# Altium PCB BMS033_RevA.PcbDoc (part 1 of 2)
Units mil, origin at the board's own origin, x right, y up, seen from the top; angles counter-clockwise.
Board outline 3000 x 3000 mil, 2 copper layers (Layer 1 - Top Layer, Layer 2 - Bottom Layer), stack 32 mil thick; 87 components, 36 nets, 183 pads, 163 vias.
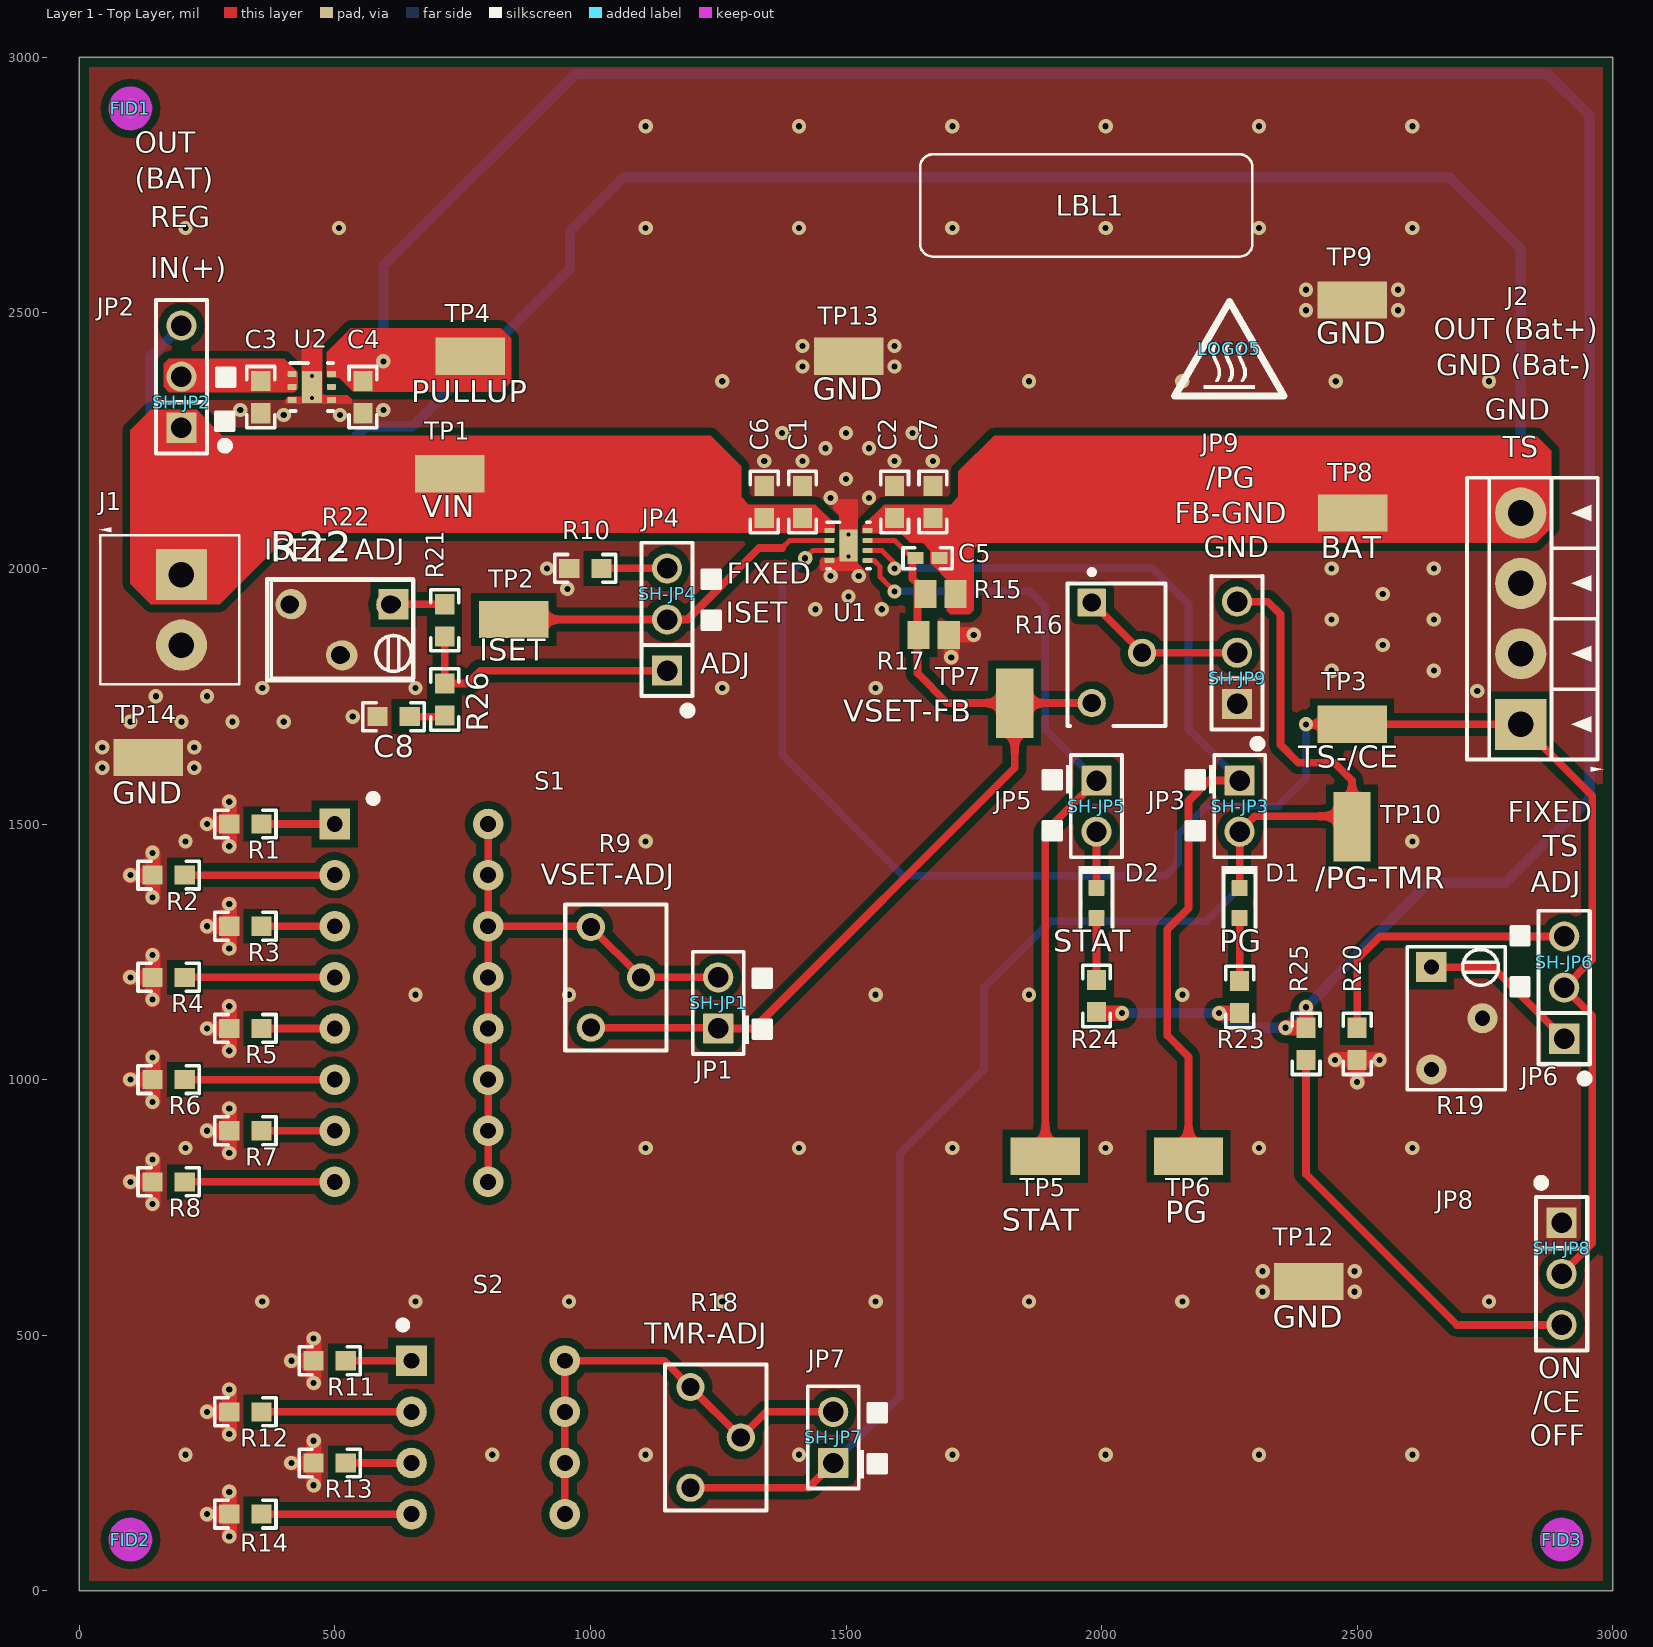
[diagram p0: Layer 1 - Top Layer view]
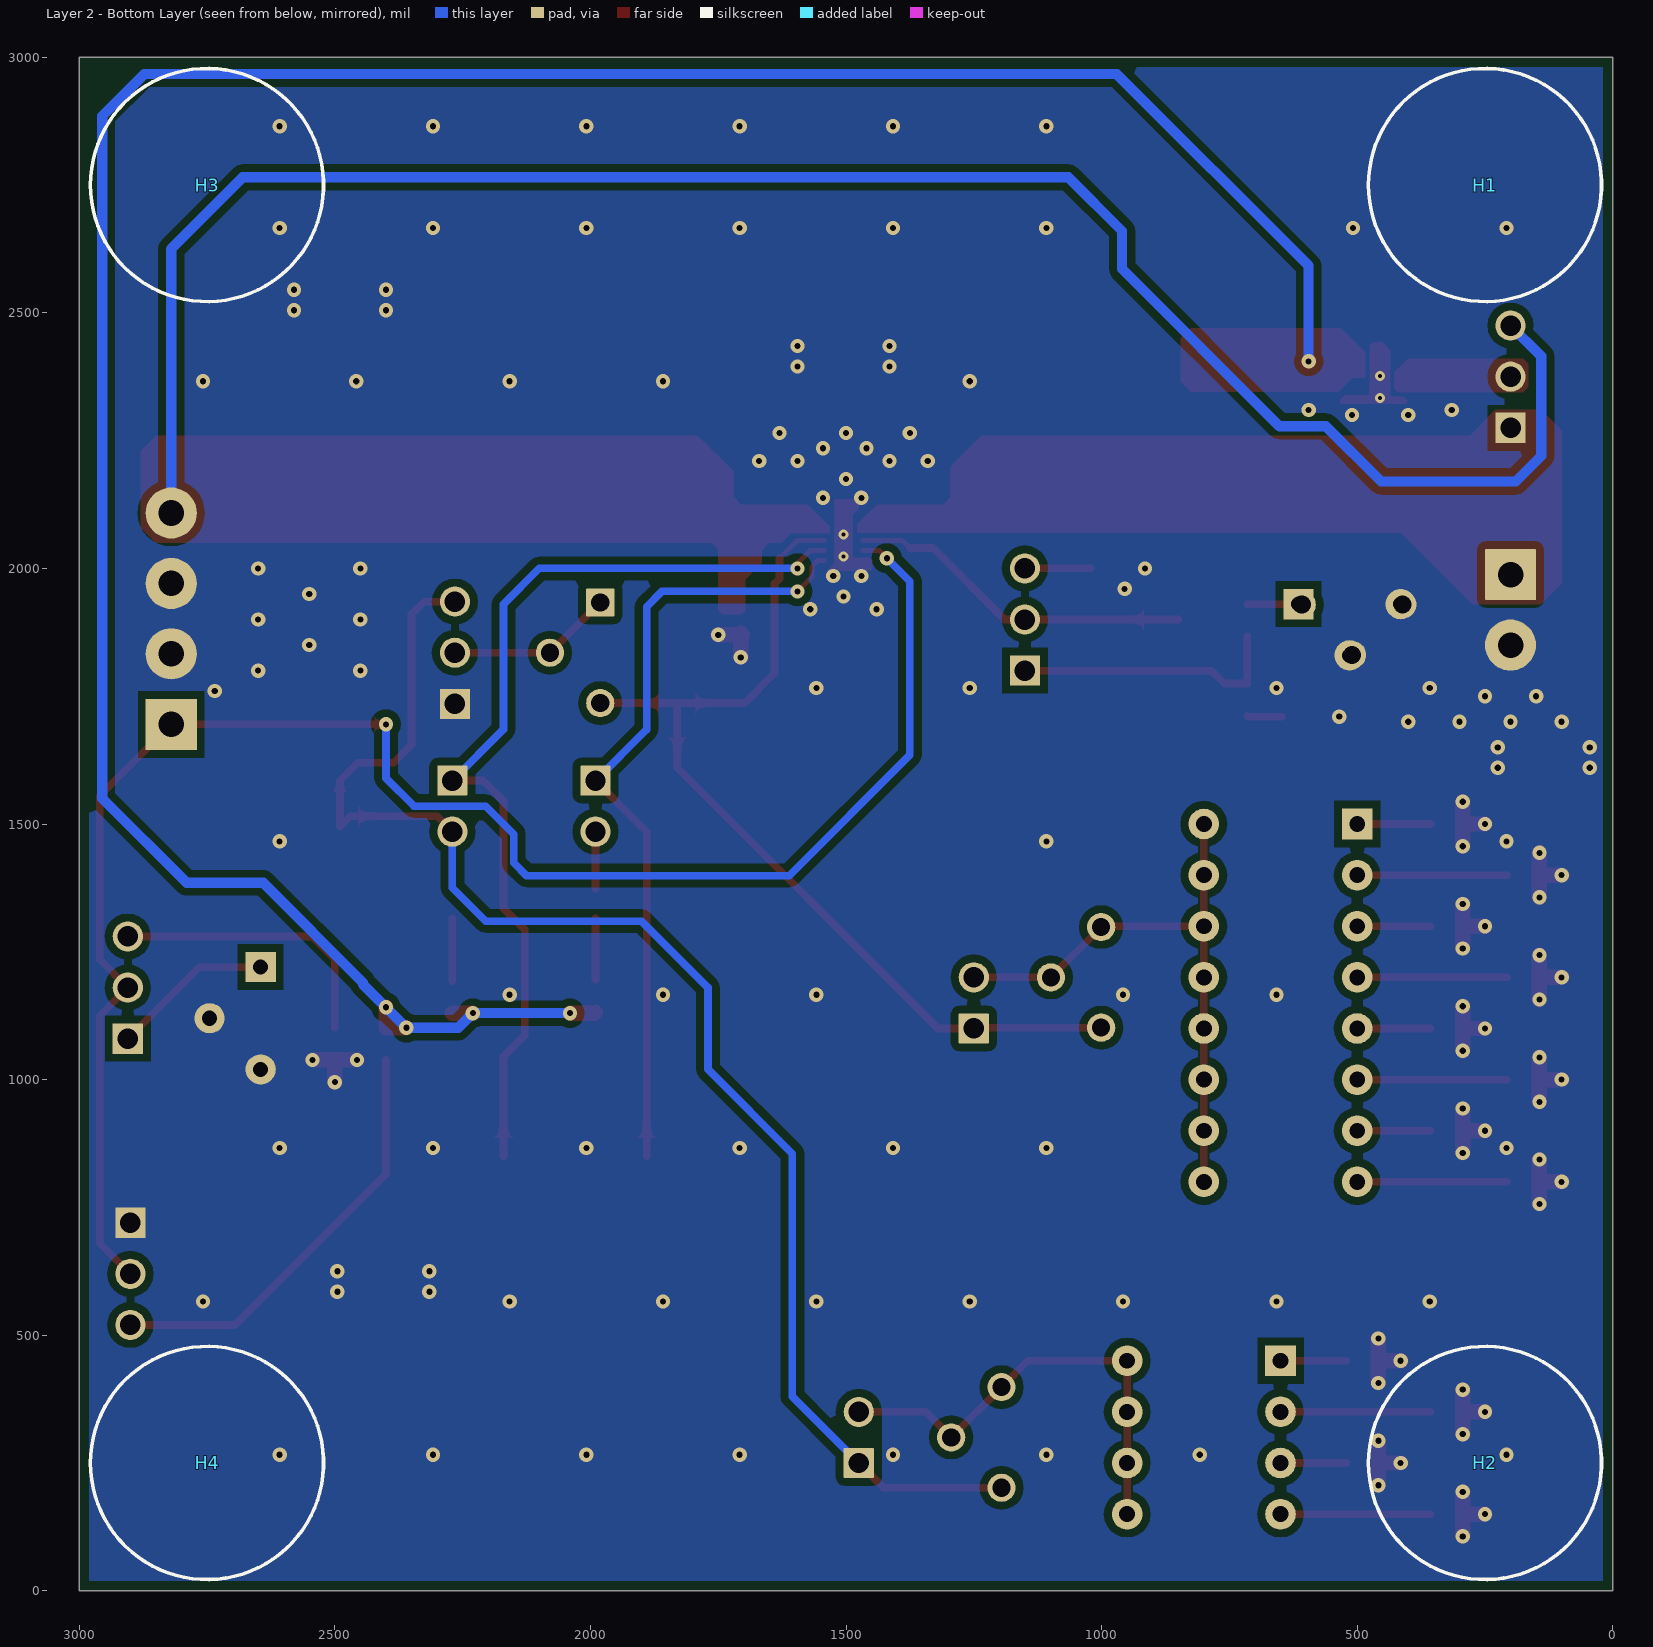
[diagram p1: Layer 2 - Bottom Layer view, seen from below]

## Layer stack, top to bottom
Top Solder: solder mask 0.4, Solder Resist, Dk 3.5
Layer 1 - Top Layer: signal copper 2.8
Dielectric 1: core 26.4, FR-4 High-TG, Dk 4.4
Layer 2 - Bottom Layer: signal copper 2.8
Bottom Solder: solder mask 0.4, Solder Resist, Dk 3.5

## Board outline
0,0 3000,0 3000,3000 0,3000

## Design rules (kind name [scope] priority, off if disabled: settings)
AcuteAngle [All] p1: minimum=4.50000000000000E+0001 checktracksonly=FALSE
AssemblyTestPointUsage [All] p1: valid=2
BoardOutlineClearance BoardOutlineClearance_MountingHoles [OnCopper and InComponentClass('Mounting Holes')] p1: gap=40 ignorepadtopadclearanceinfootprint=FALSE
BoardOutlineClearance BoardOutlineClearance_Poly [OnCopper and IsPoly] p2: gap=20 ignorepadtopadclearanceinfootprint=FALSE
BoardOutlineClearance [OnCopper and Not InComponentClass('Logo') and not InComponentClass('FiducialMark') and not InRegion(1000,500,4000,800) and not InPoly] p3: gap=20 ignorepadtopadclearanceinfootprint=FALSE
Clearance Clearance_Keepouts [((IsTrack Or IsArc) And Not InPoly) And IsFree and IsKeepOut vs ((IsTrack Or IsArc) And Not InPoly) And IsFree and IsKeepOut] p1: gap=0 ignorepadtopadclearanceinfootprint=FALSE
Clearance Clearance_Poly [InPolygon] p2: gap=15 ignorepadtopadclearanceinfootprint=FALSE
Clearance Clearance_FiducialMark [IsKeepOut and InComponentClass('FiducialMark') vs IsPad and InComponentClass('FiducialMark')] p3: gap=0 ignorepadtopadclearanceinfootprint=FALSE
Clearance [All] p4: gap=7.87 ignorepadtopadclearanceinfootprint=FALSE except(0: Arc-Hole Track-Hole SMDPad-Hole THPad-Hole Via-Hole Fill-Hole Poly-Hole Region-Hole Text-Hole)
ComponentClearance ComponentClearance_MountingHoles_FiducialMarks [InComponentClass('Mounting Holes') vs InComponentClass('FiducialMark')] p1: gap=50 collisioncheckmode=3 verticalgap=10 showdistances=FALSE
ComponentClearance ComponentClearance_Shunt [InComponentClass('Header') vs InComponentClass('Shunt')] p2: gap=0 collisioncheckmode=3 verticalgap=0 showdistances=FALSE
ComponentClearance ComponentClearance_Logo [InComponentClass('Logo')] p3: gap=50 collisioncheckmode=3 verticalgap=10 showdistances=FALSE
ComponentClearance ComponentClearance_ScrewToNut [(HasFootprint('NY PMS 440 0025 PH')) vs (HasFootprint('Keystone_1902C'))] p4: gap=5 collisioncheckmode=3 verticalgap=10 showdistances=FALSE
ComponentClearance "ComponentClearance_R15and R15X" [InComponent('R15') vs InComponent('R15X')] p5: gap=0 collisioncheckmode=3 verticalgap=0 showdistances=FALSE
ComponentClearance ComponentClearance_MountingHoles [InComponentClass('Mounting Holes')] p6: gap=250 collisioncheckmode=3 verticalgap=100000 showdistances=FALSE
ComponentClearance ComponentClearance_SmallPassives [HasFootprint('0201*') or HasFootprint('0402*') or HasFootprint('0508') or HasFootprint('0603*') or HasFootprint('0612') or HasFootprint('0805*') or HasFootprint('0815*') or HasFootprint('0830*') or HasFootprint('1206*') or HasFootprint('1210*') or HasFootprint('1808*') or HasFootprint('1812*') or HasFootprint('1825*') or HasFootprint('2010*') or HasFootprint('2220*') or HasFootprint('2225*') or HasFootprint('2512*') or HasFootprint('2728*') or HasFootprint('3518*') vs HasFootprint('0201*') or HasFootprint('0402*') or HasFootprint('0508') or HasFootprint('0603*') or HasFootprint('0612') or HasFootprint('0805*') or HasFootprint('0815*') or HasFootprint('0830*') or HasFootprint('1206*') or HasFootprint('1210*') or HasFootprint('1808*') or HasFootprint('1812*') or HasFootprint('1825*') or HasFootprint('2010*') or HasFootprint('2220*') or HasFootprint('2225*') or HasFootprint('2512*') or HasFootprint('2728*') or HasFootprint('3518*')] p7: gap=14.96 collisioncheckmode=3 verticalgap=10 showdistances=FALSE
ComponentClearance ComponentClearance_THtoSMT [IsThruComponent vs IsSMTComponent] p8: gap=40 collisioncheckmode=3 verticalgap=30 showdistances=FALSE
ComponentClearance ComponentClearance_THtoTH [IsThruComponent vs IsThruComponent] p9: gap=30 collisioncheckmode=3 verticalgap=30 showdistances=FALSE
ComponentClearance [All] p10: gap=30 collisioncheckmode=3 verticalgap=10 showdistances=FALSE
DiffPairsRouting [All] p1: maxlimit=100 minlimit=10 mostfreqgap=10 toplayer_minwidth=15 toplayer_maxwidth=15 toplayer_prefwidth=15 bottomlayer_minwidth=15 bottomlayer_maxwidth=15 bottomlayer_prefwidth=15 maxuncoupledlength=1000
FabricationTestPointUsage TestPointUsage [All] p1: valid=2 allowmultiple=FALSE
FabricationTestpoint Testpoint [All] p1: side=3 testpointundercomponent=TRUE minsize=40 maxsize=100 preferedsize=60 minholesize=0 maxholesize=40 preferedholesize=32 testpointgrid=1 allowsidetop=TRUE allowsidebottom=TRUE usegrid=TRUE gridtolerance=0.01
FanoutControl Fanout_LCC [IsLCC] p1: bgadir=Out bgaviamode=Centered fanoutstyle=Auto fanoutdirection=Alternating viagrid=1 // Fanout_LCC (Default Rule)
FanoutControl Fanout_BGA [IsBGA] p2: bgadir=Out bgaviamode=Centered fanoutstyle=Auto fanoutdirection=Alternating viagrid=1 // Fanout_BGA (Default Rule)
FanoutControl Fanout_Default [All] p4: bgadir=Out bgaviamode=Centered fanoutstyle=Auto fanoutdirection=Alternating viagrid=1 // Fanout_Default (Default Rule)
FanoutControl Fanout_Small [(CompPinCount < 5)] p5: bgadir=Out bgaviamode=Centered fanoutstyle=Auto fanoutdirection=OutThenIn viagrid=1 // Fanout_Small (Default Rule)
HoleSize [All] p1: absolutevalues=TRUE maxlimit=251 minlimit=7.87 maxpercent=80.000 minpercent=20.000
MinimumAnnularRing MinimumAnnularRing_ThermalPadVias [IsVia and InAnyComponent] p1: minimumring=5.91
MinimumAnnularRing [All] p2: minimumring=8
MinimumSolderMaskSliver MinimumSolderMaskSliver_Logo [InComponentClass('Logo') vs InComponentClass('Logo')] p1: minsoldermaskwidth=0.7
MinimumSolderMaskSliver [All] p2: minsoldermaskwidth=3.94
PlaneConnect [All] p1: planeconnectstyle=Relief reliefexpansion=10 reliefentries=4 reliefconductorwidth=10 reliefairgap=10
PolygonConnect [All] p1: connectstyle=Direct reliefconductorwidth=10 reliefentries=4 polygonreliefangle="90 Angle" airgapwidth=10
RoutingVias ThermalPadVias [IsVia and InAnyComponent] p1: holewidth=7.87 width=19.68 viastyle="Through Hole" minholewidth=7.87 minwidth=19.68 maxholewidth=12.99 maxwidth=23.62
RoutingVias [All] p2: holewidth=16 width=34 viastyle="Through Hole" minholewidth=7.87 minwidth=26 maxholewidth=40 maxwidth=65
SilkToBoardRegionClearance [Not ((IsComment or IsDesignator) And (Hide <> 'False')) and not InRegion(1000,500,4000,800)] p1:
SilkToSilkClearance SilkToSilkClearance_Pb-FreeLogo [(HasFootprint('Pb-Free_Overlay_Medium') OR HasFootprint('Pb-Free_Overlay_Small')) vs (HasFootprint('Pb-Free_Overlay_Medium') OR HasFootprint('Pb-Free_Overlay_Small'))] p1: silktosilkclearance=0
SilkToSilkClearance [All] p2: silktosilkclearance=4
SilkToSolderMaskClearance SilkToComponentPadClearance [(IsPad or IsFill or IsRegion) and InAnycomponent] p1: minsilkscreentomaskgap=5 clearancetoexposedcopper=TRUE
SilkToSolderMaskClearance "Silk to Solder Mask Opening" [All] p2: minsilkscreentomaskgap=4 clearancetoexposedcopper=FALSE
SolderMaskExpansion [All] p1: expansion=1.97 istentingtop=FALSE
Width [All] p1: maxlimit=150 minlimit=6 preferedwidth=10 checkconnectedcopper=TRUE
15 further rules are at their usual default settings.

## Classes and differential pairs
component class BMS033_RevA: C1 C2 C3 C4 C5 C6 C7 C8 D1 D2 J1 J2 JP1 JP2 JP3 JP4 JP5 JP6 JP7 JP8 JP9 JP12 R1 R2 R3 R4 R5 R6 R7 R8 R9 R10 R11 R12 R13 R14 R15 R16 R17 R18 R19 R20 R21 R22 R23 R24 R25 R26 S1 S2 SH-JP1 SH-JP2 SH-JP3 SH-JP4 SH-JP5 SH-JP6 SH-JP7 SH-JP8 SH-JP9 TP1 TP2 TP3 TP4 TP5 TP6 TP7 TP8 TP9 TP10 TP12 TP13 TP14 U1 U2
component class BMS033_RevA_Hardware: FID1 FID2 FID3 H1 H2 H3 H4 LBL1 LOGO5 Logo? ZZ1 ZZ2 ZZ3 ZZ4
component class FiducialMark: FID1 FID2 FID3
component class AssemblyNote: ZZ1 ZZ2 ZZ3 ZZ4
component class Label: LBL1
component class Header: JP1 JP2 JP3 JP4 JP5 JP6 JP7 JP8 JP9 JP12
component class Shunt: SH-JP1 SH-JP2 SH-JP3 SH-JP4 SH-JP5 SH-JP6 SH-JP7 SH-JP8 SH-JP9

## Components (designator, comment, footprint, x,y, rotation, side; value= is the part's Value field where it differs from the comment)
C1 "GRT188R61H105ME13D" 0603 1415,2130 r90 top value=1uF
C2 "GCM188R71C105KA64D" 0603 1595,2130 r90 top value=1uF
C3 "GRT188R61H105ME13D" 0603 355,2335 r270 top value=1uF
C4 "GCM188R71C105KA64D" 0603 555,2335 r270 top value=1uF
C5 "04025A101FAT2A" 0402 1659.51,2020 r180 top value=100pF
C6 "GRT188R61H105ME13D" 0603 1340,2130 r90 top value=1uF
C7 "GCM188R71C105KA64D" 0603 1670,2130 r90 top value=1uF
C8 "C0603C104K9PAC7867" 0603 615,1710 r0 top value=4700pF
D1 "LTST-C193TGKT-5A" LTST-C193_Green_S 2270,1345.47 r90 top value=Green
D2 "LTST-C193TGKT-5A" LTST-C193_Green_S 1990,1345.47 r90 top value=Green
FID1 "Fiducial" Fiducial10-20 100,2900 r0 top
FID2 "Fiducial" Fiducial10-20 100,100 r0 top
FID3 "Fiducial" Fiducial10-20 2900,100 r0 top
H1 "SJ-5303 (CLEAR)" Bumpon_SJ5003Transparent 250,2750 r180 bottom
H2 "SJ-5303 (CLEAR)" Bumpon_SJ5003Transparent 250,250 r180 bottom
H3 "SJ-5303 (CLEAR)" Bumpon_SJ5003Transparent 2750,2750 r180 bottom
H4 "SJ-5303 (CLEAR)" Bumpon_SJ5003Transparent 2750,250 r180 bottom
J1 "ED555/2DS" TERM_BLK_ED555-2DS 200,1988 r270 top
J2 "ED555/4DS" TERM_BLK_ED555-4DS 2820,1695 r90 top
JP1 "PEC02SAAN" CONN_PEC02SAAN 1250,1150 r90 top
JP2 "PEC03SAAN" CONN_PEC03SAAN 200,2375 r90 top
JP3 "PEC02SAAN" CONN_PEC02SAAN 2270,1535 r270 top
JP4 "PEC03SAAN" CONN_PEC03SAAN 1150,1900 r90 top
JP5 "PEC02SAAN" CONN_PEC02SAAN 1990,1535 r270 top
JP6 "PEC03SAAN" CONN_PEC03SAAN 2905,1180 r90 top
JP7 "PEC02SAAN" CONN_PEC02SAAN 1475,300 r90 top
JP8 "PEC03SAAN" CONN_PEC03SAAN 2900,620 r270 top
JP9 "PEC03SAAN" CONN_PEC03SAAN 2265,1835 r90 top
LBL1 "THT-14-423-10" Label_650x200 1970,2710 r0 top
LOGO5 "CAUTION HOT SURFACE" IEC_HotSurface_Small 2250,2430 r0 top
R1 "RC0603FR-0775KL" 0603 325,1500 r0 top value=100k
R2 "RC0603FR-0733KL" 0603 175,1400 r0 top value=82.0k
R3 "RC0603FR-0727K4L" 0603 325,1300 r0 top value=62.0k
R4 "RC0603FR-0722K1L" 0603 175,1200 r0 top value=36.0k
R5 "RC0603FR-077K5L" 0603 325,1100 r0 top value=27.0k
R6 "RC0603FR-075K6L" 0603 175,1000 r0 top value=24.0k
R7 "RC0603FR-073K32L" 0603 325,900 r0 top value=18.0k
R8 "RC0603JR-070RL" 0603 175,800 r0 top value=0
R9 "PV37W503C01B00" Bourns_PV37W 1050,1200 r0 top value="50k Ohm"
R10 "RC0603FR-07750RL" 0603 990,2000 r180 top value=750
R11 "RC0603FR-0733KL" 0603 490,450 r0 top value=33.0k
R12 "RC0603FR-0718K2L" 0603 325,350 r0 top value=18.2k
R13 "RC0603FR-077K5L" 0603 490,250 r0 top value=7.50k
R14 "RC0603JR-070RL" 0603 325,150 r0 top value=0
R15 "RT0805BRD07604KL" 0805L 1685,1950 r0 top value=604k
R16 "PV37W504C01B00" FP-PV37W504C01B00_PTH_3-MFG 2029.21,1831.26 r90 top
R17 "RT0805BRD07604KL" 0805L 1671.5,1870 r180 top value=604k
R18 "PV37W503C01B00" Bourns_PV37W 1245,300 r0 top value="50k Ohm"
R19 "3266W-1-203LF" TRIM_3266W 2645,1220 r0 top value=20k
R20 "CRCW060310K0FKEA" 0603 2500,1070 r90 top value=10.0k
R21 "CRCW0603301RFKEA" 0603 715,1898.5 r270 top value=301
R22 "PV37W502C01B00" Bourns_PV37W 510,1880 r270 top
R22 "3266W-1-203LF" TRIM_3266W 615,1930 r270 top value=20k
R23 "RC0603FR-071KL" 0603 2270,1161.54 r270 top value=1.00k
R24 "RC0603FR-071KL" 0603 1990,1163.5 r270 top value=1.00k
R25 "CRCW060310K0FKEA" 0603 2400,1070 r90 top value=10.0k
R26 "CRCW06032K00FKEA" 0603 715,1743.5 r270 top value=2.00k
S1 "76SB08ST" SW_76SB08ST 650,1150 r0 top
S2 "78B04ST" SW_78B04ST 800,300 r0 top
SH-JP1 "SNT-100-BK-G" SNT-100-BK-G 1250,1150 r90 top value=1x2
SH-JP2 "SNT-100-BK-G" SNT-100-BK-G 200,2325 r90 top value=1x2
SH-JP3 "SNT-100-BK-G" SNT-100-BK-G 2270,1535 r270 top value=1x2
SH-JP4 "SNT-100-BK-G" SNT-100-BK-G 1150,1950 r90 top value=1x2
SH-JP5 "SNT-100-BK-G" SNT-100-BK-G 1990,1535 r270 top value=1x2
SH-JP6 "SNT-100-BK-G" SNT-100-BK-G 2905,1230 r90 top value=1x2
SH-JP7 "SNT-100-BK-G" SNT-100-BK-G 1475,300.09 r90 top value=1x2
SH-JP8 "SNT-100-BK-G" SNT-100-BK-G 2900,670 r90 top value=1x2
SH-JP9 "SNT-100-BK-G" SNT-100-BK-G 2265,1785 r90 top value=1x2
TP1 "S1751-46" Harwin_S1751-46 725,2185 r0 top
TP2 "S1751-46" Harwin_S1751-46 850,1900 r180 top
TP3 "S1751-46" Harwin_S1751-46 2490,1695 r180 top
TP4 "S1751-46" Harwin_S1751-46 765,2415 r180 top
TP5 "S1751-46" Harwin_S1751-46 1890,850 r0 top
TP6 "S1751-46" Harwin_S1751-46 2170,850 r0 top
TP7 "S1751-46" Harwin_S1751-46 1830,1736.57 r270 top
TP8 "S1751-46" Harwin_S1751-46 2491.61,2108.39 r180 top
TP9 "S1751-46" Harwin_S1751-46 2490,2525 r180 top
TP10 "S1751-46" Harwin_S1751-46 2490,1495 r270 top
TP12 "S1751-46" Harwin_S1751-46 2405,605 r180 top
TP13 "S1751-46" Harwin_S1751-46 1505,2415 r180 top
TP14 "S1751-46" Harwin_S1751-46 135,1630 r180 top
U1 "BQ25170DSG" DSG0008A 1505,2045 r0 top
U2 "TPS7B8133QDRVRQ1" DRV0006A 455,2355 r0 top
ZZ1 "This Assembly Note is for PCB labels only" AssemblyNoteLabel 77.83,3440.99 r0 top
ZZ2 "These assemblies are ESD sensitive, ESD precautions shall be observed." AssemblyNote 77.83,3332.11 r0 top
ZZ3 "These assemblies must be clean and free from flux and all contaminants. Use of no clean flux is not acceptable." AssemblyNote 77.83,3243.55 r0 top
ZZ4 "These assemblies must comply with workmanship standards IPC-A-610 Class 2, unless otherwise specified." AssemblyNote 77.83,3154.99 r0 top

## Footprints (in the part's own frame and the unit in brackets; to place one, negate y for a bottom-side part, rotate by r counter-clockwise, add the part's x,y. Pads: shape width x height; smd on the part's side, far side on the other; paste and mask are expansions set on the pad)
0402 [mm] "0402 from SM-752 data"
  rect 0.8x0.6 smd: 1(-0.6,0) 2(0.6,0)
  silkscreen extent -1.22,-0.52 1.22,0.52, body extent -0.55,-0.3 0.55,0.3, height 0.6
0603 [mm] "0603 from SM-752 data"
  rect 1x0.95 smd: 1(-0.8,0) 2(0.8,0)
  silkscreen extent -1.52,-0.69 1.52,0.69, body extent -0.87,-0.47 0.87,0.47, height 1
0805L [mm] "0805 from SM-752 data"
  rect 1.1x1.4 smd: 1(-0.75,0) 2(0.75,0)
  body extent -1.1,-0.72 1.1,0.72, height 1.45
AssemblyNote [mil] "Assembly Note"
AssemblyNoteLabel [mil] "Assembly Note for PCB Labels"
Bourns_PV37W [mm] "TH, 3-Leads, Body 6.71x4.5mm"
  round 1.4 hole 0.9: 1(-1.25,2.5) 2(1.25,0) 3(-1.25,-2.5)
  silkscreen extent -2.52,-3.63 2.52,3.63, body extent -2.44,-3.54 2.44,3.54, height 8.39
Bumpon_SJ5003Transparent [mil] "3M Hemispherical Bumpon transparent"
  round 1 on Mech4: 0(0,0)
  silkscreen extent -228,-228 228,228, body extent -219,-219 219,219, height 197
CONN_PEC02SAAN [mm] "SULLINS"
  rrect7% 1.5x1.5 hole 1.016: 1(-1.27,0)
  round 1.5 hole 1.016: 2(1.27,0)
  silkscreen extent -2.54,-1.52 2.54,1.27, body extent -2.54,-1.27 2.54,1.27, height 8.38
CONN_PEC03SAAN [mm] "SULLINS"
  rect 1.5x1.5 hole 1.016: 1(-2.54,0)
  round 1.5 hole 1.016: 2(0,0) 3(2.54,0)
  silkscreen extent -3.81,-2.36 3.81,1.27, body extent -3.84,-1.3 3.84,1.3, height 8.38
DRV0006A [mm] "SON, 6-Leads, Body 2x2mm, Pitch 0.65mm, Thermal Pad 1.6x1mm, TI Recommended"
  rrect33% 0.45x0.3 smd: 1(-0.975,0.65) 2(-0.975,0) 3(-0.975,-0.65) 4(0.975,-0.65) 5(0.975,0) 6(0.975,0.65)
  rrect14% 1x0.7 on Top Paste: 7(0,-0.45) 7(0,0.45)
  rrect10% 1x1.6 smd paste-0.5: 7(0,0)
  silkscreen extent -1.05,-1.2 1.05,1.2, body extent -1.05,-1.05 1.05,1.05, height 0.81
DSG0008A [mm] "SON, 8-Leads, Body 2x2mm, Pitch 0.5mm, Thermal Pad 1.6x0.9mm, TI Recommended"
  rrect40% 0.5x0.25 smd: 1(-0.95,0.75) 2(-0.95,0.25) 3(-0.95,-0.25) 4(-0.95,-0.75) 5(0.95,-0.75) 6(0.95,-0.25) 7(0.95,0.25) 8(0.95,0.75)
  rrect14% 0.9x0.7 on Top Paste: 9(0,-0.45) 9(0,0.45)
  rrect11% 0.9x1.6 smd paste-0.45: 9(0,0)
  silkscreen extent -1.07,-1.15 1.07,1.15, body extent -1,-1 1,1, height 0.77
Fiducial10-20 [mm]
  round 1 smd mask+0.5: 1(0,0)
  Layer 1 - Top Layer keep-out circle w1.178: c0,0 r0.5
FP-PV37W504C01B00_PTH_3-MFG [mm]
  rrect7% 1.4x1.4 hole 0.9 paste-1000 mask+0: 1(2.595,1.23)
  round 1.4 hole 0.9 paste-1000 mask+0: 2(0.095,-1.27) 3(-2.405,1.23)
  silkscreen extent -3.54,-2.44 4.22,2.44, body extent -3.64,-2.54 3.64,2.54, height 0.25
Harwin_S1751-46 [mm] "Test Point, Body 3.25x1.65mm"
  rect 3.45x1.85 smd: 1(0,0)
  body extent -1.62,-0.82 1.63,0.82, height 2.05
IEC_HotSurface_Small [mil]
  silkscreen extent -107,-93 107,92
Label_650x200 [mil] "Thermal Transfer Label"
  round 1 on Mech13: 0(0,0)
  silkscreen extent -325,-100 325,100, body extent -325,-100 325,100, height 1
LTST-C193_Green_S [mm] "SMD, 2-Leads, Body 1.6x0.8mm"
  rrect12% 0.8x0.8 smd: 1(-0.75,0) 2(0.75,0)
  silkscreen extent -1.2,-0.9 1.85,0.9, body extent -0.85,-0.45 0.85,0.45, height 0.45
SNT-100-BK-G [mil] "Samtec STEP model"
  round 1 on Mech3: 0(0,0)
  body extent -100,-50 100,50, height 344
SW_76SB08ST [mil] "Switch, DIP Slide, 8Pos"
  rect 60x60 hole 31: 1(-150,350)
  round 60 hole 31: 2(-150,250) 3(-150,150) 4(-150,50) 5(-150,-50) 6(-150,-150) 7(-150,-250) 8(-150,-350) 9(150,-350) 10(150,-250) 11(150,-150) 12(150,-50) 13(150,50) 14(150,150) 15(150,250) 16(150,350)
  silkscreen extent -82,393 -68,407, body extent -195,-446 195,446, height 321
SW_78B04ST [mil] "Switch, DIP Slide, 4Pos"
  rect 60x60 hole 31: 1(-150,150)
  round 60 hole 31: 2(-150,50) 3(-150,-50) 4(-150,-150) 5(150,-150) 6(150,-50) 7(150,50) 8(150,150)
  silkscreen extent -174,213 -160,227, body extent -195,-245 195,245, height 337
TERM_BLK_ED555-2DS [mil]
  rrect4% 100x100 hole 50: 1(0,0)
  round 100 hole 50: 2(138,0)
  silkscreen extent -93,-161 215,113, body extent -69,-150 207,106, height 323
TERM_BLK_ED555-4DS [mm]
  rect 2.54x2.54 hole 1.27: 1(0,0)
  round 2.54 hole 1.27: 2(3.5,0) 3(7,0) 4(10.5,0)
  silkscreen extent -2.36,-4.09 12.25,2.67, body extent -1.75,-3.8 12.25,2.7, height 8.2
TRIM_3266W [mm] "Bourns 3266W series REV 08/10"
  rect 1.5x1.5 hole 0.75: 1(0,0)
  round 1.5 hole 0.75: 2(2.54,-2.54) 3(0,-5.08)
  silkscreen extent -1.2,-6.09 3.68,1.01, body extent -1.2,-6.09 3.68,1.01, height 8.45

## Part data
C1 C3 C6: library part CMP-0081784-1, "CAP, CERM, 1 µF, 50 V,+/- 20%, X5R, AEC-Q200 Grade 3, 0603", Cap_Case=0603, Manufacturer=MuRata, Supplier Part Number 1=490-12331-1-ND, TempCo=X5R, Tolerance_%=20%, Value2=50V, ValueDisplayed=1µF
C2 C4 C7: library part CMP-0007136-5, "CAP, CERM, 1 uF, 16 V, +/- 10%, X7R, AEC-Q200 Grade 1, 0603", Cap_Case=0603, Manufacturer=MuRata, Supplier Part Number 1=490-5241-6-ND, TempCo=X7R, Tolerance_%=10%, Value1=Unknown, Value2=16V, ValueDisplayed=1uF
C5: library part CMP-0006196-2, "CAP, CERM, 100 pF, 50 V, +/- 1%, C0G/NP0, 0402", Cap_Case=0402, Manufacturer=AVX, Supplier Part Number 1=478-3658-1-ND, TempCo=C0G/NP0, Tolerance_%=1%, Value1=Unknown, Value2=50V, ValueDisplayed=DNI
C8: library part CMP-0007354-5, "CAP, CERM, 4700 pF, 50 V, +/- 10%, X5R, 0603", Cap_Case=0603, Manufacturer=MuRata, PartNumber=GRM188R61H472KA01D, Supplier Part Number 1=GRM188R61H472KA01D-ND, TempCo=X5R, Tolerance_%=10%, Value1=Unknown, Value2=50V, ValueDisplayed=4700pF
D1 D2: library part CMP-0080580-2, "LED, Green, SMD", Color=Green, Manufacturer=Lite-On, Power_TotalModule=76mW, Value1=0.076W, Value2=2.8V
FID1 FID2 FID3: library part CMP-0077181-1, "Fiducial mark.  There is nothing to buy or mount.", Manufacturer=N/A
H1 H2 H3 H4: library part CMP-0003620-1, "Bumpon, Hemisphere, 0.44 X 0.20, Clear", Manufacturer=3M, Supplier Part Number 1=SJ5303-7-ND
J1: library part CMP-0074913-1, "Terminal Block, 3.5mm Pitch, 2x1, TH", Color=Grey, Current_A=6A, Manufacturer="On-Shore Technology", Supplier Part Number 1=ED1514-ND, Voltage_V=150V
J2: library part CMP-0074917-1, "Terminal Block, 3.5mm Pitch, 4x1, TH", Color=Grey, Current_A=6A, Manufacturer="On-Shore Technology", Supplier Part Number 1=ED1516-ND, Voltage_V=150V
JP1 JP3 JP5 JP7: library part CMP-0002337-1, "Header, 100mil, 2x1, Tin, TH", Color=Black, Current_A=3A, Manufacturer="Sullins Connector Solutions", Supplier Part Number 1=S1012E-02-ND, Voltage_V=1.8kV
JP2 JP4 JP6 JP8 JP9: library part CMP-0002338-1, "Header, 100mil, 3x1, Tin, TH", Color=Black, Current_A=3A, Manufacturer="Sullins Connector Solutions", Supplier Part Number 1=S1012E-03-ND, Voltage_V=1.8kV
LBL1: library part CMP-0003625-1, "Thermal Transfer Printable Labels, 0.650\" W x 0.200\" H - 10,000 per roll", Manufacturer=Brady, Supplier Part Number 1=97C5133
LOGO5: library part CMP-0074837-1, "IEC 61010-1 Hot Surface Warning"
R1: library part CMP-0022735-5, "RES, 100 k, 1%, 0.1 W, 0603", Manufacturer=Yageo, PartNumber=RC0603FR-07100KL, Power_W=100mW, Supplier Part Number 1=311-100KHRCT-ND, TempCo="100 ppm/C", Tolerance_%=1%, Value2=0.1W, Value_Code=100k
R2: library part CMP-0023292-5, "RES, 82.0 k, 1%, 0.1 W, 0603", Manufacturer=Yageo, PartNumber=RC0603FR-0782KL, Power_W=100mW, Supplier Part Number 1=311-82.0KHRCT-ND, TempCo="100 ppm/C", Tolerance_%=1%, Value2=0.1W, Value_Code=82k0, ValueDisplayed=82.0k
R3: library part CMP-0023220-5, "RES, 62.0 k, 1%, 0.1 W, 0603", Manufacturer=Yageo, PartNumber=RC0603FR-0762KL, Power_W=100mW, Supplier Part Number 1=311-62.0KHRCT-ND, TempCo="100 ppm/C", Tolerance_%=1%, Value2=0.1W, Value_Code=62k0, ValueDisplayed=62.0k
R4: library part CMP-0023057-5, "RES, 36.0 k, 1%, 0.1 W, 0603", Manufacturer=Yageo, PartNumber=RC0603FR-0736KL, Power_W=100mW, Supplier Part Number 1=311-36.0KHRCT-ND, TempCo="100 ppm/C", Tolerance_%=1%, Value2=0.1W, Value_Code=36k0, ValueDisplayed=36.0k
R5: library part CMP-0022966-5, "RES, 27.0 k, 1%, 0.1 W, 0603", Manufacturer=Yageo, PartNumber=RC0603FR-0727KL, Power_W=100mW, Supplier Part Number 1=311-27.0KHRCT-ND, TempCo="100 ppm/C", Tolerance_%=1%, Value2=0.1W, Value_Code=27k0, ValueDisplayed=27.0k
R6: library part CMP-0022945-5, "RES, 24.0 k, 1%, 0.1 W, 0603", Manufacturer=Yageo, PartNumber=RC0603FR-0724KL, Power_W=100mW, Supplier Part Number 1=311-24.0KHRCT-ND, TempCo="100 ppm/C", Tolerance_%=1%, Value2=0.1W, Value_Code=24k0, ValueDisplayed=24.0k
R7: library part CMP-0022852-5, "RES, 18.0 k, 1%, 0.1 W, 0603", Manufacturer=Yageo, PartNumber=RC0603FR-0718KL, Power_W=100mW, Supplier Part Number 1=311-18.0KHRCT-ND, TempCo="100 ppm/C", Tolerance_%=1%, Value2=0.1W, Value_Code=18k0, ValueDisplayed=18.0k
R8 R14: library part CMP-0025885-5, "RES, 0, 5%, 0.1 W, 0603", Manufacturer=Yageo, Power_W=100mW, Supplier Part Number 1=311-0.0GRCT-ND, TempCo="200 ppm/C", Tolerance_%=5%, Value2=0.1W, Value_Code=0000, ValueDisplayed=0
R9 R18: library part CMP-0001794-2, "Trimmer Potentiometer, Lead Sealed Type Multiturn PV37 Series, TH", Manufacturer=Bourns, Supplier Part Number 1=490-2984-ND
R10: library part CMP-0023266-5, "RES, 750, 1%, 0.1 W, 0603", Manufacturer=Yageo, Power_W=100mW, Supplier Part Number 1=311-750HRCT-ND, TempCo="100 ppm/C", Tolerance_%=1%, Value2=0.1W, Value_Code=750R, ValueDisplayed=750
R11: library part CMP-0023037-5, "RES, 33.0 k, 1%, 0.1 W, 0603", Manufacturer=Yageo, Power_W=100mW, Supplier Part Number 1=311-33.0KHRCT-ND, TempCo="100 ppm/C", Tolerance_%=1%, Value2=0.1W, Value_Code=33k0, ValueDisplayed=33.0k
R12: library part CMP-0022850-5, "RES, 18.2 k, 1%, 0.1 W, 0603", Manufacturer=Yageo, Power_W=100mW, Supplier Part Number 1=311-18.2KHRCT-ND, TempCo="100 ppm/C", Tolerance_%=1%, Value2=0.1W, Value_Code=18k2, ValueDisplayed=18.2k
R13: library part CMP-0023279-5, "RES, 7.50 k, 1%, 0.1 W, 0603", Manufacturer=Yageo, Power_W=100mW, Supplier Part Number 1=311-7.50KHRCT-ND, TempCo="100 ppm/C", Tolerance_%=1%, Value2=0.1W, Value_Code=7k50, ValueDisplayed=7.50k
R15 R17: library part CMP-0020221-2, "RES, 604 k, 0.1%, 0.125 W, 0805", Manufacturer="Yageo America", Power_W=125mW, Supplier Part Number 1=9983082, TempCo="25 ppm/C", Tolerance_%=0.1%, Value2=0.125W, Value_Code=604k
R16: library part CMP-0088264-1, "500 kOhms 0.25W, 1/4W PC Pins Through Hole Trimmer Potentiometer Cermet 12 Turn Top Adjustment", Manufacturer=Bourns
R19 R22: library part CMP-0002068-2, "Trimmer, 20k ohm, 0.25W, TH", Manufacturer=Bourns, Supplier Part Number 1=3266W-203LF-ND
R20 R25: library part CMP-0021998-4, "RES, 10.0 k, 1%, 0.1 W, AEC-Q200 Grade 0, 0603", Manufacturer=Vishay-Dale, Power_W=100mW, Supplier Part Number 1=541-10.0KHCT-ND, TempCo="100 ppm/C", Tolerance_%=1%, Value2=0.1W, Value_Code=10k0, ValueDisplayed=10.0k
R21: library part CMP-0022321-5, "RES, 301, 1%, 0.1 W, AEC-Q200 Grade 0, 0603", Manufacturer=Vishay-Dale, Power_W=100mW, Supplier Part Number 1=541-301HCT-ND, TempCo="100 ppm/C", Tolerance_%=1%, Value2=0.1W, Value_Code=301R, ValueDisplayed=301
R22: library part CMP-0001795-1, "Trimmer Potentiometer, Lead Sealed Type Multiturn PV37 Series, TH"
R23 R24: library part CMP-0022895-5, "RES, 1.00 k, 1%, 0.1 W, 0603", Manufacturer=Yageo, Power_W=100mW, Supplier Part Number 1=311-1.00KHRCT-ND, TempCo="100 ppm/C", Tolerance_%=1%, Value2=0.1W, Value_Code=1k00, ValueDisplayed=1.00k
R26: library part CMP-0022268-4, "RES, 2.00 k, 1%, 0.1 W, AEC-Q200 Grade 0, 0603", Manufacturer=Vishay-Dale, Power_W=100mW, Supplier Part Number 1=541-2.00KHCT-ND, TempCo="100 ppm/C", Tolerance_%=1%, Value2=0.1W, Value_Code=2k00, ValueDisplayed=2.00k
S1: library part CMP-0002117-2, "Switch, SPST 8Pos, Rocker, TH", CurrentRating_mA=150A, Manufacturer=Grayhill, Supplier Part Number 1=GH7176-ND
S2: library part CMP-0002130-2, "DIP Switch, SPST 4Pos, Slide, TH", CurrentRating_mA=150A, Manufacturer=Grayhill, Supplier Part Number 1=GH7184-ND
SH-JP1 SH-JP2 SH-JP3 SH-JP4 SH-JP5 SH-JP6 SH-JP7 SH-JP8 SH-JP9: library part CMP-0003623-3, "Shunt, 100mil, Gold plated, Black", Alternate Manufacturer=3M, Alternate PartNumber=969102-0000-DA, Manufacturer=Samtec, Supplier Part Number 1=SAM8858-ND
TP1 TP2 TP3 TP4 TP5 TP6 TP7 TP8 TP9 TP10 TP12 TP13 TP14: library part CMP-0075188-1, "Test Lead clips and hooks, SMT", Current_A=2A, Manufacturer=Harwin, Supplier Part Number 1=S1751-46-ND
U1: library part CMP-0096741-1, "800-mA Linear Battery Charger for 1-Cell Li-Ion, and LiFePO4", Digikey Part Number=296-BQ25170DSGRCT-ND, Manufacturer="Texas Instruments", Max Supply Voltage=6.6V, Min Supply Voltage=3V, Mouser Part Number=595-BQ25170DSGR, Nominal Supply Current=0.45mA, Operating Temperature Range="-40°C to +125°C", Output Voltage=4.4V, Part Number=BQ25170DSGR
U2: library part CMP-0860463-1, "Automotive 150-mA high-voltage ultra-low-IQ low-dropout (LDO) linear regulator, DRV0006A (WSON-6)", Alternate Manufacturer="Texas Instruments", Operating Temperature Range="-40 to 150 C", Rating=Automotive
ZZ1: library part CMP-0003616-3
ZZ2: library part CMP-0077236-1
ZZ3: library part CMP-0077237-1
ZZ4: library part CMP-0077238-1

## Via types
v1: diameter 28, hole 12, Layer 1 - Top Layer to Layer 2 - Bottom Layer, tented both sides, 159 vias
v2: diameter 19.68, hole 7.87, Layer 1 - Top Layer to Layer 2 - Bottom Layer, 4 vias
